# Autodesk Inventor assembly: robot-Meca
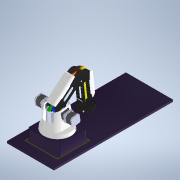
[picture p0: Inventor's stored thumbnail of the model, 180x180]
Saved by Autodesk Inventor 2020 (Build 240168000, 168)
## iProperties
Created: 2017-09
Part Number: robot-Meca
Document SubType Name: Assembly
Designer: bruno
Sending System: SolidWorks 2016
Last Author: Prof
Last Saved: 2018-10-31
Author: bruno
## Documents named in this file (11)
- C:\Users\bruno\Documents\Systèmes\Mallette Bras robotisé (273265)\Dossier ressources\Maquette Dobot SW2016\robot-Meca.iam
- C:\Users\bruno\Documents\Systèmes\Mallette Bras robotisé (273265)\Dossier ressources\Maquette Dobot SW2016\base^robot.iam
- C:\Users\bruno\Documents\Systèmes\Mallette Bras robotisé (273265)\Dossier ressources\Maquette Dobot SW2016\plateforme^robot.iam
- C:\Users\bruno\Documents\Systèmes\Mallette Bras robotisé (273265)\Dossier ressources\Maquette Dobot SW2016\bras inférieur^robot.iam
- C:\Users\bruno\Documents\Systèmes\Mallette Bras robotisé (273265)\Dossier ressources\Maquette Dobot SW2016\manivelle inférieure^robot.iam
- C:\Users\bruno\Documents\Systèmes\Mallette Bras robotisé (273265)\Dossier ressources\Maquette Dobot SW2016\biellette gauche^robot.iam
- C:\Users\bruno\Documents\Systèmes\Mallette Bras robotisé (273265)\Dossier ressources\Maquette Dobot SW2016\biellette droite^robot.iam
- C:\Users\bruno\Documents\Systèmes\Mallette Bras robotisé (273265)\Dossier ressources\Maquette Dobot SW2016\bras supérieur^robot.iam
- C:\Users\bruno\Documents\Systèmes\Mallette Bras robotisé (273265)\Dossier ressources\Maquette Dobot SW2016\basculeur^robot.iam
- C:\Users\bruno\Documents\Systèmes\Mallette Bras robotisé (273265)\Dossier ressources\Maquette Dobot SW2016\biellette avant^robot.iam
- C:\Users\bruno\Documents\Systèmes\Mallette Bras robotisé (273265)\Dossier ressources\Maquette Dobot SW2016\Stylo.iam
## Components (10 placed, 10 different names)
1. base:1 [sub-assembly] — Placage:4, Affleurement:1, Angle:1
2. plateforme:1 [sub-assembly] — Placage:3, Placage:4, Affleurement:1, Placage:5, Placage:6, Placage:7, Placage:8
3. bras inférieur:1 [sub-assembly] — Placage:7, Placage:8, Placage:9, Placage:10, Angle:1
4. manivelle inférieure:1 [sub-assembly] — Placage:1, Placage:2, Placage:3
5. biellette gauche:1 [sub-assembly] — Placage:5, Placage:6, Placage:11, Placage:16
6. biellette droite:1 [sub-assembly] — Placage:1, Placage:2, Placage:20, Placage:21
7. bras supérieur:1 [sub-assembly] — Placage:9, Placage:10, Placage:12, Placage:17, Placage:19, Placage:20, Placage:21
8. basculeur:1 [sub-assembly] — Placage:11, Placage:12, Placage:13, Placage:14, Placage:16
9. biellette avant:1 [sub-assembly] — Placage:13, Placage:14, Placage:18
10. Stylo:1 [sub-assembly] — Placage:17, Placage:18, Placage:19
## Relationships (22: Mate 20, Flush 1, Angle 1)
- Placage:1 [Mate]: manivelle inférieure:1 ↔ biellette droite:1
- Placage:2 [Mate]: manivelle inférieure:1 ↔ biellette droite:1
- Placage:3 [Mate]: plateforme:1 ↔ manivelle inférieure:1
- Placage:4 [Mate]: base:1 ↔ plateforme:1
- Affleurement:1 [Flush]: base:1 ↔ plateforme:1
- Placage:5 [Mate]: plateforme:1 ↔ biellette gauche:1
- Placage:6 [Mate]: plateforme:1 ↔ biellette gauche:1
- Placage:7 [Mate]: plateforme:1 ↔ bras inférieur:1
- Placage:8 [Mate]: plateforme:1 ↔ bras inférieur:1
- Placage:9 [Mate]: bras inférieur:1 ↔ bras supérieur:1
- Placage:10 [Mate]: bras inférieur:1 ↔ bras supérieur:1
- Placage:11 [Mate]: biellette gauche:1 ↔ basculeur:1
- Placage:12 [Mate]: bras supérieur:1 ↔ basculeur:1
- Placage:13 [Mate]: basculeur:1 ↔ biellette avant:1
- Placage:14 [Mate]: basculeur:1 ↔ biellette avant:1
- Placage:16 [Mate]: biellette gauche:1 ↔ basculeur:1
- Placage:17 [Mate]: bras supérieur:1 ↔ Stylo:1
- Placage:18 [Mate]: biellette avant:1 ↔ Stylo:1
- Placage:19 [Mate]: bras supérieur:1 ↔ Stylo:1
- Placage:20 [Mate]: biellette droite:1 ↔ bras supérieur:1
- Placage:21 [Mate]: biellette droite:1 ↔ bras supérieur:1
- Angle:1: base:1 ↔ bras inférieur:1
